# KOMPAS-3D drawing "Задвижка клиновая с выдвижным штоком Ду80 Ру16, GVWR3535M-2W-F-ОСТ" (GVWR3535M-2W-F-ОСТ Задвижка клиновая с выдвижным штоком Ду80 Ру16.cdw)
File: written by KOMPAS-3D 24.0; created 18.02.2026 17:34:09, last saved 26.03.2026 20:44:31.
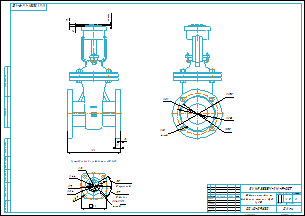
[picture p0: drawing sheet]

Document properties: Автор: R2D2; Форматы листов документа: A2; Полное имя файла: GVWR3535M-2W-F-ОСТ Задвижка клиновая с выдвижным штоком Ду80 Ру16.m3d; Масса: 20.5; Наименование: Задвижка клиновая с выдвижным штоком Ду80 Ру16; Количество листов документа: 1; Примечание: D040-09830

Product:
- Part/product: Задвижка клиновая с выдвижным штоком Ду80 Ру16  | designation GVWR3535M-2W-F-ОСТ
    Масса: 20.5
    Раздел спецификации: Прочие изделия
    Примечание: D040-09830

Views: Проекционный вид 2, Проекционный вид 3
Referenced files in E:\Работа\Зайцев\GVWR2121M-2W-F-ОСТ Задвижка клиновая с видвижным штоком Ду50-300 Ру16\DN80\: GVWR2121M-2W-F-ОСТ Задвижка клиновая с видвижным штоком Ду80 Ру16.m3d
Referenced files in E:\Работа\Зайцев\Для компаса\: чертеж DN.ru А3.cdt
Referenced files in E:\Работа\Зайцев\GVWR3535M-2W-F-ОСТ Задвижка клиновая 30нж941нж DN.ru Ду50-200 Ру16\исходные данные\DN80\dn80\: GVWR3535M-2W-F-ОСТ Задвижка клиновая с выдвижным штоком Ду80 Ру16.m3d
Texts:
  GVWR3535M-2W-F-ОСТ
  Присоединение привода тип АК (А)
  чертеж DN.ru А3.cdt
  Задвижка клиновая с
  выдвижным штоком Ду80
  Ру16
  Задвижка клиновая с выдвижным штоком Ду80 Ру16
  GVWR3535M-2W-F-ОСТ Задвижка клиновая с выдвижным штоком Ду80 Ру16
Dimensions and other numbers on the sheet: 0; 3; 4; 195; 80; 18; 4 отв.; 160; 135; 100; 5 кулачков; 5 впадин; 14 (М12); 13,5; 104; 70; 44; 32; 1:2; 1; 2; 20,5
